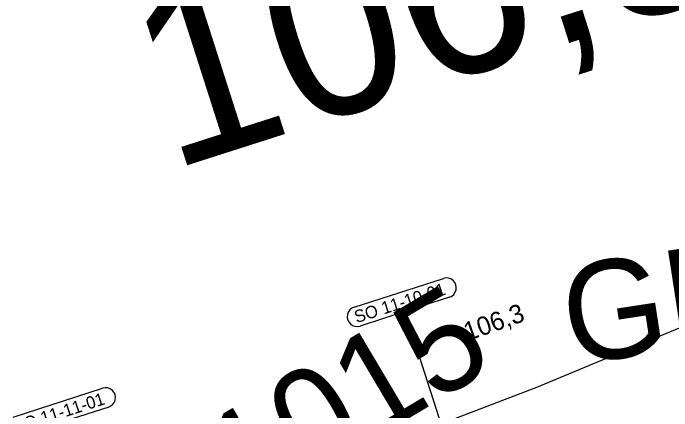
# Model space of a CAD drawing. Extents: x -759005 to -757278, y -1175311 to -1173953.
# Drawn here: x -758408.3 to -758275, y -1174763.8 to -1174683.4 of the extents above; entities that cross this region are included whole.
import ezdxf

# ---------------------------------------------------------------- set-up
doc = ezdxf.new("R2010")
doc.units = 0
for name, color, linetype in [('_NOR-popis', 7, 'Continuous'), ('G_Obvod stavby', 7, 'Continuous'), ('Vrstva 53', 7, 'Continuous'), ('Vrstva 62', 7, 'Continuous'), ('Vrstva 7', 7, 'Continuous')]:
    doc.layers.add(name, color=color, linetype=linetype)

msp = doc.modelspace()

# ---------------------------------------------------------------- linework, layer by layer
at = {"layer": '_NOR-popis'}
for points in [[(-758339.33, -1174742.8), (-758321.24, -1174736.98)], [(-758320.02, -1174740.79), (-758329.06, -1174743.7), (-758315.87, -1174784.63)], [(-758329.06, -1174743.7), (-758338.1, -1174746.61)], [(-758408.27, -1174765.01), (-758390.18, -1174759.18)], [(-758388.95, -1174762.99), (-758398, -1174765.9), (-758378.82, -1174825.45)]]:
    msp.add_lwpolyline(points, dxfattribs=at)
for centre, start, end in [((-758320.63, -1174738.88), 287.8533, 107.854), ((-758338.71, -1174744.71), 107.854, 287.8547), ((-758389.57, -1174761.09), 287.8533, 107.854)]:
    msp.add_arc(centre, 2, start, end, dxfattribs=at)
at = {"layer": 'G_Obvod stavby'}
msp.add_lwpolyline([(-758392.72, -1174840.76), (-758391.23, -1174838.56), (-758368.37, -1174821.64), (-758340.31, -1174807.33), (-758320.27, -1174796.89), (-758301, -1174790.21), (-758267.96, -1174782.93), (-758224.96, -1174775.27), (-758184.87, -1174772.83), (-758142.71, -1174770.26), (-758089.84, -1174768.68), (-758106.02, -1174731.44), (-758149.09, -1174725.67), (-758199.62, -1174726.6), (-758225.76, -1174732.36), (-758252.17, -1174738.18), (-758254.97, -1174739.34), (-758266.58, -1174744.16), (-758279.45, -1174749.49), (-758302.42, -1174759.02), (-758331.68, -1174770.24), (-758367.17, -1174799.81), (-758405.64, -1174832.2)], dxfattribs=at)

# ---------------------------------------------------------------- texts
at = {"layer": '_NOR-popis'}
for s, p in [('SO 11-10-01', (-758338.8, -1174746.05)), ('SO 11-11-01', (-758407.74, -1174768.26))]:
    msp.add_text(s, height=2.5, rotation=17.854, dxfattribs=at).set_placement(p)
at = {"layer": 'Vrstva 53'}
for s, rotation, p in [('GB1016', 8.7502, (-758295.49, -1174754.64)), ('GB1015', 30.6913, (-758394.68, -1174804.71))]:
    msp.add_text(s, height=20, rotation=rotation, dxfattribs=at).set_placement(p)
at = {"layer": 'Vrstva 62'}
msp.add_text('106,3', height=36, rotation=17.7485, dxfattribs=at).set_placement((-758376.56, -1174715.23))
at = {"layer": 'Vrstva 7'}
msp.add_text('106,3', height=3.75, rotation=19.4575, dxfattribs=at).set_placement((-758316.36, -1174749.69))

doc.saveas('drawing.dxf')
